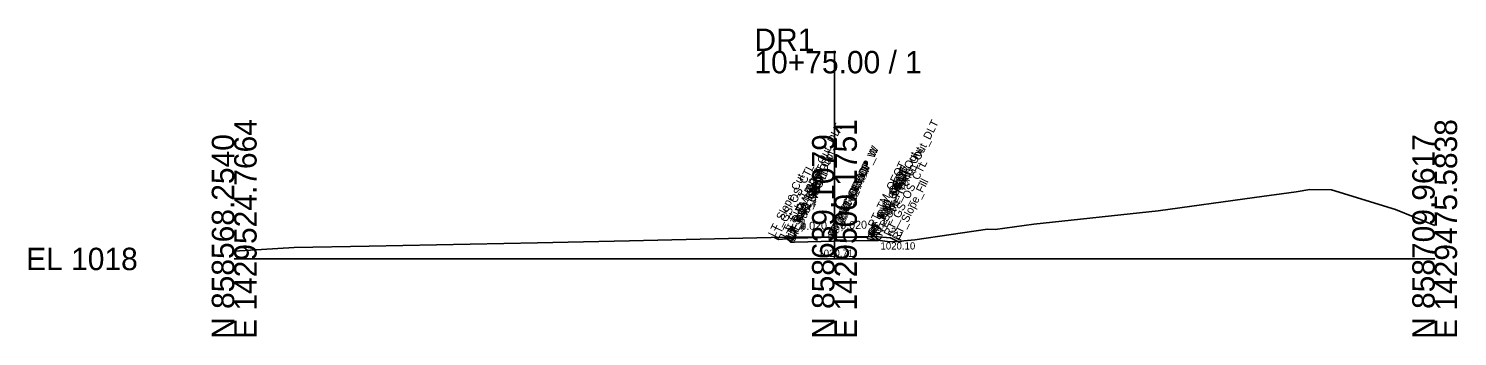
# Model space of a CAD drawing. Extents: x -26 to 1303, y -10 to 1029.
# Drawn here: x 1124.3 to 1302.8, y 990.3 to 1028.8 of the extents above; entities that cross this region are included whole.
import ezdxf

# ---------------------------------------------------------------- set-up
doc = ezdxf.new("R2010")
doc.units = 0
for name, color, linetype in [('Default', 7, 'Continuous'), ('Exist Cross Section Cell', 7, 'Continuous'), ('Exist XS Center Line Elevation Label', 7, 'Continuous'), ('Exist XS Ground Line', 7, 'Continuous'), ('Prop CMT Pvmt Course 1', 7, 'Continuous'), ('Prop CMT Pvmt Course 2', 7, 'Continuous'), ('Prop CMT Pvmt Surface', 7, 'Continuous'), ('Prop CMT Pvmt Surface Overlay', 7, 'Continuous'), ('Prop CMT Shld Paved Course 1', 7, 'Continuous'), ('Prop CMT Shld Paved Course 2', 7, 'Continuous'), ('Prop CMT Slope Grass', 7, 'Continuous'), ('Prop CMT Subgrade Earthwork', 7, 'Continuous'), ('Prop XS Dump Level', 7, 'Continuous'), ('Prop XS EOT Tick Mark', 7, 'Continuous'), ('Prop XS SE Text', 7, 'Continuous'), ('Prop XS Side Slope Text', 7, 'Continuous')]:
    doc.layers.add(name, color=color, linetype=linetype)

msp = doc.modelspace()

# ---------------------------------------------------------------- linework, layer by layer
at = {"layer": 'Exist Cross Section Cell'}
for p, q in [((1225, 1000), (1225, 1026.01)), ((1150, 1000), (1225, 1000)), ((1225, 1000), (1300, 1000))]:
    msp.add_line(p, q, dxfattribs=at)
at = {"layer": 'Exist XS Ground Line'}
msp.add_lwpolyline([(1150, 1000.96), (1157.5, 1001.41), (1166.88, 1001.61), (1187.88, 1002.03), (1199.39, 1002.25), (1218.83, 1002.71), (1220, 1002.74), (1225, 1002.71), (1229.09, 1002.68), (1229.16, 1002.52), (1231.91, 1002.15), (1232.75, 1002.18), (1235.05, 1002.41), (1244.11, 1003.72), (1245.1, 1003.68), (1249.92, 1004.34), (1265.44, 1006.02), (1277.49, 1007.67), (1282.68, 1008.4), (1284.41, 1008.67), (1287.1, 1008.66), (1295.1, 1006.17), (1300, 1004.19)], dxfattribs=at)
at = {"layer": 'Prop CMT Pvmt Course 1'}
for points in [[(1225, 1002.71), (1220, 1002.61)], [(1225, 1002.71), (1230, 1002.81)]]:
    msp.add_lwpolyline(points, dxfattribs=at)
at = {"layer": 'Prop CMT Pvmt Course 2'}
for points in [[(1220, 1002.11), (1225, 1002.21)], [(1230, 1002.31), (1225, 1002.21)]]:
    msp.add_lwpolyline(points, dxfattribs=at)
at = {"layer": 'Prop CMT Pvmt Surface'}
for points in [[(1225, 1002.71), (1220, 1002.61)], [(1225, 1002.71), (1230, 1002.81)]]:
    msp.add_lwpolyline(points, dxfattribs=at)
at = {"layer": 'Prop CMT Pvmt Surface Overlay'}
for points in [[(1225, 1002.71), (1220, 1002.61)], [(1225, 1002.71), (1230, 1002.81)]]:
    msp.add_lwpolyline(points, dxfattribs=at)
at = {"layer": 'Prop CMT Shld Paved Course 1'}
for points in [[(1220, 1002.61), (1219.74, 1002.35)], [(1230, 1002.81), (1230.25, 1002.56)]]:
    msp.add_lwpolyline(points, dxfattribs=at)
at = {"layer": 'Prop CMT Shld Paved Course 2'}
for points in [[(1219.74, 1002.35), (1219.49, 1002.1)], [(1219.49, 1002.1), (1220, 1002.11)], [(1219.74, 1002.35), (1219.74, 1002.35)], [(1230.49, 1002.32), (1230, 1002.31)], [(1230.25, 1002.56), (1230.25, 1002.56)], [(1230.25, 1002.56), (1230.49, 1002.32)]]:
    msp.add_lwpolyline(points, dxfattribs=at)
at = {"layer": 'Prop CMT Slope Grass'}
for q in [(1232, 1002.65), (1233.37, 1002.24)]:
    msp.add_line((1233.09, 1002.1), q, dxfattribs=at)
for points in [[(1220, 1002.61), (1218, 1002.45), (1217.53, 1002.68)], [(1230, 1002.81), (1232, 1002.65)]]:
    msp.add_lwpolyline(points, dxfattribs=at)
at = {"layer": 'Prop CMT Subgrade Earthwork'}
for points in [[(1225, 1002.21), (1220, 1002.11), (1219.49, 1002.1), (1219.06, 1002.53)], [(1225, 1002.21), (1230, 1002.31), (1230.49, 1002.32), (1230.91, 1002.73)]]:
    msp.add_lwpolyline(points, dxfattribs=at)
at = {"layer": 'Prop XS EOT Tick Mark'}
for points in [[(1220, 1002.61), (1220, 1003.61)], [(1230, 1002.81), (1230, 1003.81)]]:
    msp.add_lwpolyline(points, dxfattribs=at)

# ---------------------------------------------------------------- texts
at = {"layer": 'Default'}
for s, height, p in [('1020.10', 0.9, (1230.75, 1001.18)), ('-', 0.0001, (1150, 1000))]:
    msp.add_text(s, height=height, dxfattribs=at).set_placement(p)
at = {"layer": 'Exist Cross Section Cell'}
for s, p in [('DR1', (1215, 1026.01)), ('10+75.00 / 1', (1215, 1023.21)), ('EL 1018', (1124, 998.6))]:
    msp.add_text(s, height=2.8, dxfattribs=at).set_placement(p)
for s, p in [('E 1429524.7664', (1152.8, 990)), ('E 1429500.1751', (1227.8, 990)), ('E 1429475.5838', (1302.8, 990)), ('N 858568.2540', (1150, 990)), ('N 858639.1079', (1225, 990)), ('N 858709.9617', (1300, 990))]:
    msp.add_text(s, height=2.8, rotation=90, dxfattribs=at).set_placement(p)
at = {"layer": 'Exist XS Center Line Elevation Label'}
msp.add_text('1020.71', height=0.9, dxfattribs=at).set_placement((1222.99, 1000.26))
at = {"layer": 'Prop XS Dump Level'}
for s, p in [('LT_Sub_Trench_Out_DLT', (1219.06, 1002.53)), ('RT_Sub_Trench_Out_DLT', (1230.94, 1002.77)), ('RT_PV1_OEEOP_W', (1225, 1002.58)), ('LT_PV1_OEEOP_W', (1225, 1002.58)), ('LT_Sub_Trench_Out', (1219.49, 1002.1)), ('LT_PS2_Shelf_Out', (1219.74, 1002.35)), ('RT_PS2_Shelf_Out', (1230.25, 1002.56)), ('RT_Sub_Trench_Out', (1230.49, 1002.32)), ('LT_Slope_Cut', (1217.53, 1002.68)), ('LT_GS_OS_CTL', (1218, 1002.45)), ('LT_PS2_OEOP', (1219.74, 1002.35)), ('LT_TM_OEOT', (1220, 1003.61)), ('LT_PV1_OEOT', (1220, 1002.61)), ('LT_PV2_OEOT', (1220, 1002.36)), ('LT_Sub_OEOT', (1220, 1002.11)), ('RT_PV2_OEEOP', (1225, 1002.46)), ('LT_PV2_OEEOP', (1225, 1002.46)), ('RT_Sub_OEEOP', (1225, 1002.21)), ('LT_Sub_OEEOP', (1225, 1002.21)), ('RT_TM_OEOT', (1230, 1003.81)), ('RT_PV1_OEOT', (1230, 1002.81)), ('RT_PV2_OEOT', (1230, 1002.56)), ('RT_Sub_OEOT', (1230, 1002.31)), ('RT_PS2_OEOP', (1230.25, 1002.56)), ('RT_GS_OS_CTL', (1232, 1002.73)), ('PV1_PGL_W', (1225, 1002.58)), ('RT_Slope_Fill', (1233.04, 1002.21)), ('PV1_PGL', (1225, 1002.71))]:
    msp.add_text(s, height=1, rotation=63.5833, dxfattribs=at).set_placement(p)
at = {"layer": 'Prop XS SE Text'}
for p in [(1220.73, 1003.62), (1225.73, 1003.72)]:
    msp.add_text('0.020', height=1, rotation=1.1458, dxfattribs=at).set_placement(p)
at = {"layer": 'Prop XS Side Slope Text'}
msp.add_text('2:1', height=1, rotation=333.4349, dxfattribs=at).set_placement((1231.71, 1003.14))

doc.saveas('drawing.dxf')
